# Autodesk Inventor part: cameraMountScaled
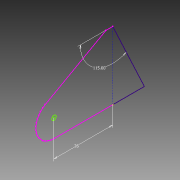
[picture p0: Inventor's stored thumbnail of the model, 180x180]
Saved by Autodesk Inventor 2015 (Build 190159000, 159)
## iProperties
Created: 2015-02
Part Number: cameraMountScaled
Material: Generic
Document SubType Name: Modeling
Designer: sungeun
Density: 1 g/cm^3
Appearance: Default
Author: sungeun
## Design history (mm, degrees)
feature "cameraMount"
sketch "Sketch6"
  geometry: L1 (0, 0)-(0, 26) reference; L2 (30, 0)-(30, 3) reference; L3 (14.986, 29.899)-(30, 3) reference; L4 (14.253, 30.991)-(14.986, 29.899) reference; L5 (13.351, 31.947)-(14.253, 30.991) reference; L6 (12.304, 32.744)-(13.351, 31.947) reference; L7 (11.142, 33.357)-(12.304, 32.744) reference; L8 (9.894, 33.773)-(11.142, 33.357) reference; L9 (8.596, 33.978)-(9.894, 33.773) reference; L10 (7.281, 33.968)-(8.596, 33.978) reference; L11 (5.986, 33.742)-(7.281, 33.968) reference; L12 (4.745, 33.308)-(5.986, 33.742) reference; L13 (3.592, 32.676)-(4.745, 33.308) reference; L14 (2.558, 31.864)-(3.592, 32.676) reference; L15 (1.671, 30.893)-(2.558, 31.864) reference; L16 (0.955, 29.791)-(1.671, 30.893) reference; L17 (0.429, 28.585)-(0.955, 29.791) reference; L18 (0.108, 27.31)-(0.429, 28.585) reference; L19 (0, 26)-(0.108, 27.31) reference; L20 (30, 0)-(0, -13.989); L21 (0, -13.989)-(0, 0); L22 (0, 0)-(30, 0); C1 r 0.996 at (8, 26); 1 further point
  constraints: 6 end point, 1 centre point, 1 horizontal, 1 vertical
  dimensions: "d3" = 115 deg angle of L2 L20; "d6" = 26 distance from line of L22 C1.centre
extrude "Extrusion2" new body sketch "Sketch6" distance "d7" = 54; taper "d8" = 0 deg
body "Solid2"
